(* Logix 5000 project; controller R21 vendor 1 type 14 code 96 rev 21.11; software revision 21.00; part 2 of 5 *)

ADD_ON_INSTRUCTION PSDNP3EventG20V05   (* revision 1.0, vendor ProSoft Technology Inc *)
VAR_IN_OUT
   EventBuffer : PSDNP3MasterEvent[1]; {required}
END_VAR
VAR_INPUT
   BufferSize : DINT; {required}
   CurrentBufferIndex : DINT; {required}
   Reset : BOOL; {required}
   OutstationNodeAddress : INT; {required}
   OutstationIPAddress0 : INT; {required}
   OutstationIPAddress1 : INT; {required}
   OutstationIPAddress2 : INT; {required}
   OutstationIPAddress3 : INT; {required}
END_VAR
VAR_IN_OUT
   DNP3StaticObject : DINT[1]; {required}
END_VAR
VAR_INPUT
   MaxtElementCount : DINT; {required}
END_VAR
VAR_OUTPUT
   EventsProcessed : DINT; {access Read Only, visible}
   LastElementIndex : DINT; {access Read Only, visible}
   LastValue : DINT; {access Read Only, visible}
   LastStatus : SINT; {access Read Only, visible}
   CurrentUnloadIndex : DINT; {access Read Only, visible}
END_VAR
VAR
   UnloadIndex : DINT; {access None}
   EnableInTemp : BOOL; {access None}
   InitialScan : BOOL; {access None}
   EntryValidForProcessing : BOOL; {access None}
   ElementIndex : DINT; {access None}
   NextIndex : DINT; {access None}
   ResetPulse : BOOL; {access None}
   ResetONS : BOOL; {access None}
END_VAR

ROUTINE Logic   (* ladder *)
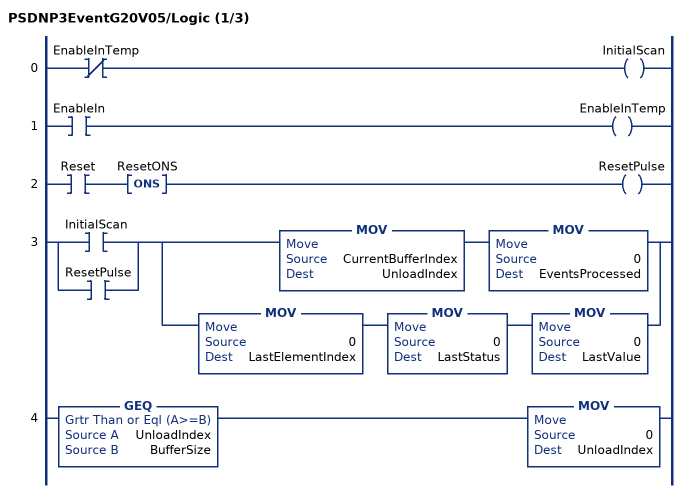
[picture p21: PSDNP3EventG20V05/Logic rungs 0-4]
   0: XIO(EnableInTemp)OTE(InitialScan);
   1: XIC(EnableIn)OTE(EnableInTemp);
   2: XIC(Reset)ONS(ResetONS)OTE(ResetPulse);
   3: [XIC(InitialScan) ,XIC(ResetPulse) ][MOV(CurrentBufferIndex,UnloadIndex) MOV(0,EventsProcessed) ,MOV(0,LastElementIndex) MOV(0,LastStatus) MOV(0,LastValue) ];
   4: GEQ(UnloadIndex,BufferSize)MOV(0,UnloadIndex);
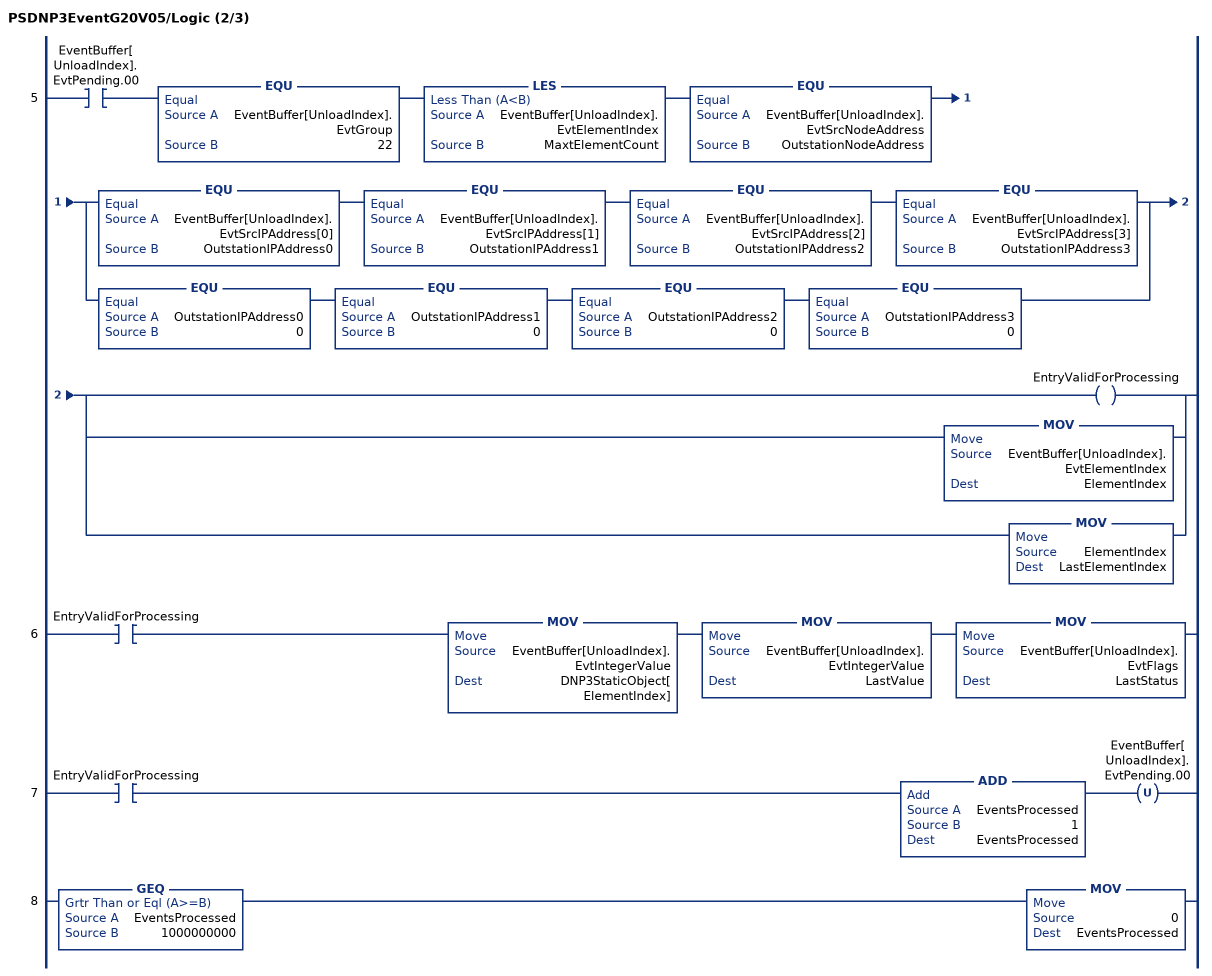
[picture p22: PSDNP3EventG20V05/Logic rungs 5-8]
   5: XIC(EventBuffer[UnloadIndex].EvtPending.00)EQU(EventBuffer[UnloadIndex].EvtGroup,22)LES(EventBuffer[UnloadIndex].EvtElementIndex,MaxtElementCount)EQU(EventBuffer[UnloadIndex].EvtSrcNodeAddress,OutstationNodeAddress)[EQU(EventBuffer[UnloadIndex].EvtSrcIPAddress[0],OutstationIPAddress0) EQU(EventBuffer[UnloadIndex].EvtSrcIPAddress[1],OutstationIPAddress1) EQU(EventBuffer[UnloadIndex].EvtSrcIPAddress[2],OutstationIPAddress2) EQU(EventBuffer[UnloadIndex].EvtSrcIPAddress[3],OutstationIPAddress3) ,EQU(OutstationIPAddress0,0) EQU(OutstationIPAddress1,0) EQU(OutstationIPAddress2,0) EQU(OutstationIPAddress3,0) ][OTE(EntryValidForProcessing) ,MOV(EventBuffer[UnloadIndex].EvtElementIndex,ElementIndex) ,MOV(ElementIndex,LastElementIndex) ];
   6: XIC(EntryValidForProcessing)MOV(EventBuffer[UnloadIndex].EvtIntegerValue,DNP3StaticObject[ElementIndex])MOV(EventBuffer[UnloadIndex].EvtIntegerValue,LastValue)MOV(EventBuffer[UnloadIndex].EvtFlags,LastStatus);
   7: XIC(EntryValidForProcessing)ADD(EventsProcessed,1,EventsProcessed)OTU(EventBuffer[UnloadIndex].EvtPending.00);
   8: GEQ(EventsProcessed,1000000000)MOV(0,EventsProcessed);
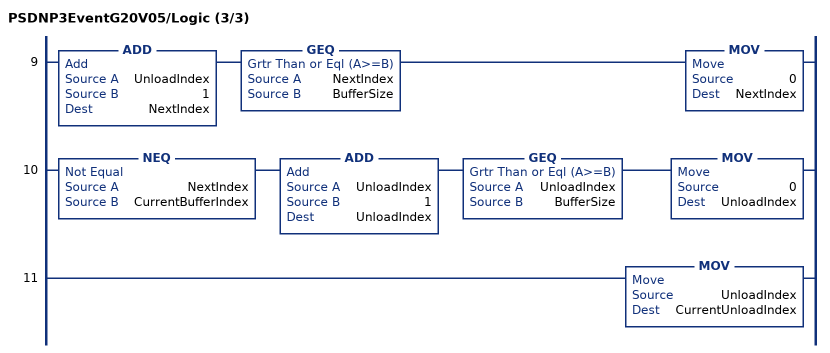
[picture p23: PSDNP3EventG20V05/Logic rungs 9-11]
   9: ADD(UnloadIndex,1,NextIndex)GEQ(NextIndex,BufferSize)MOV(0,NextIndex);
   10: NEQ(NextIndex,CurrentBufferIndex)ADD(UnloadIndex,1,UnloadIndex)GEQ(UnloadIndex,BufferSize)MOV(0,UnloadIndex);
   11: MOV(UnloadIndex,CurrentUnloadIndex);
END_ROUTINE
END_ADD_ON_INSTRUCTION

ADD_ON_INSTRUCTION PSDNP3EventG20V06   (* revision 1.0, vendor ProSoft Technology Inc *)
VAR_IN_OUT
   EventBuffer : PSDNP3MasterEvent[1]; {required}
END_VAR
VAR_INPUT
   BufferSize : DINT; {required}
   CurrentBufferIndex : DINT; {required}
   Reset : BOOL; {required}
   OutstationNodeAddress : INT; {required}
   OutstationIPAddress0 : INT; {required}
   OutstationIPAddress1 : INT; {required}
   OutstationIPAddress2 : INT; {required}
   OutstationIPAddress3 : INT; {required}
END_VAR
VAR_IN_OUT
   DNP3StaticObject : INT[1]; {required}
END_VAR
VAR_INPUT
   MaxtElementCount : DINT; {required}
END_VAR
VAR_OUTPUT
   EventsProcessed : DINT; {access Read Only, visible}
   LastElementIndex : DINT; {access Read Only, visible}
   LastValue : DINT; {access Read Only, visible}
   LastStatus : SINT; {access Read Only, visible}
   CurrentUnloadIndex : DINT; {access Read Only, visible}
END_VAR
VAR
   UnloadIndex : DINT; {access None}
   EnableInTemp : BOOL; {access None}
   InitialScan : BOOL; {access None}
   EntryValidForProcessing : BOOL; {access None}
   ElementIndex : DINT; {access None}
   NextIndex : DINT; {access None}
   ResetPulse : BOOL; {access None}
   ResetONS : BOOL; {access None}
END_VAR

ROUTINE Logic   (* ladder *)
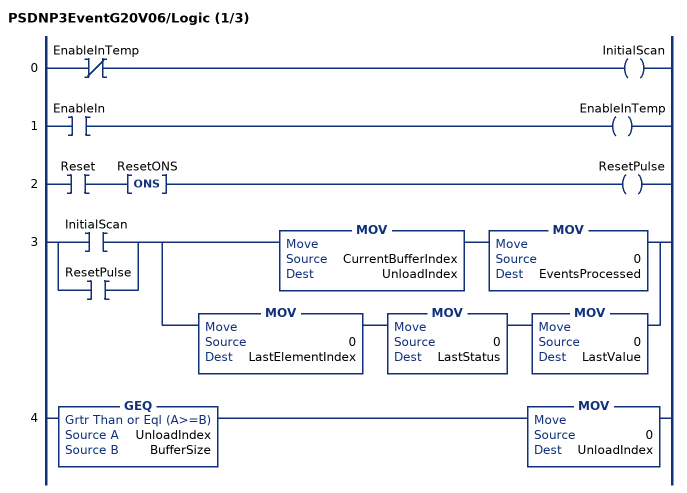
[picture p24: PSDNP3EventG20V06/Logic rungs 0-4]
   0: XIO(EnableInTemp)OTE(InitialScan);
   1: XIC(EnableIn)OTE(EnableInTemp);
   2: XIC(Reset)ONS(ResetONS)OTE(ResetPulse);
   3: [XIC(InitialScan) ,XIC(ResetPulse) ][MOV(CurrentBufferIndex,UnloadIndex) MOV(0,EventsProcessed) ,MOV(0,LastElementIndex) MOV(0,LastStatus) MOV(0,LastValue) ];
   4: GEQ(UnloadIndex,BufferSize)MOV(0,UnloadIndex);
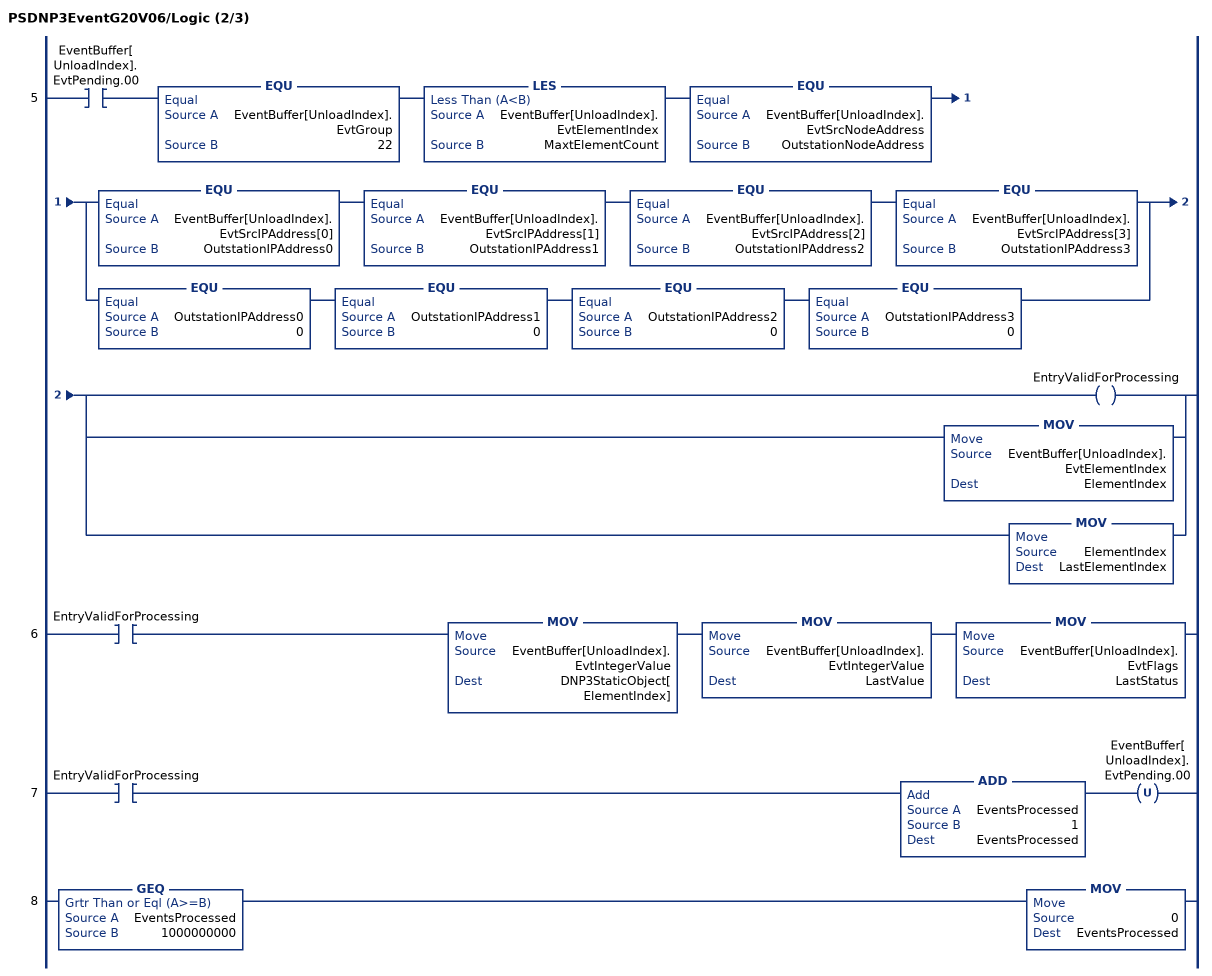
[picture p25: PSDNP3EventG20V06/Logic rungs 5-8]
   5: XIC(EventBuffer[UnloadIndex].EvtPending.00)EQU(EventBuffer[UnloadIndex].EvtGroup,22)LES(EventBuffer[UnloadIndex].EvtElementIndex,MaxtElementCount)EQU(EventBuffer[UnloadIndex].EvtSrcNodeAddress,OutstationNodeAddress)[EQU(EventBuffer[UnloadIndex].EvtSrcIPAddress[0],OutstationIPAddress0) EQU(EventBuffer[UnloadIndex].EvtSrcIPAddress[1],OutstationIPAddress1) EQU(EventBuffer[UnloadIndex].EvtSrcIPAddress[2],OutstationIPAddress2) EQU(EventBuffer[UnloadIndex].EvtSrcIPAddress[3],OutstationIPAddress3) ,EQU(OutstationIPAddress0,0) EQU(OutstationIPAddress1,0) EQU(OutstationIPAddress2,0) EQU(OutstationIPAddress3,0) ][OTE(EntryValidForProcessing) ,MOV(EventBuffer[UnloadIndex].EvtElementIndex,ElementIndex) ,MOV(ElementIndex,LastElementIndex) ];
   6: XIC(EntryValidForProcessing)MOV(EventBuffer[UnloadIndex].EvtIntegerValue,DNP3StaticObject[ElementIndex])MOV(EventBuffer[UnloadIndex].EvtIntegerValue,LastValue)MOV(EventBuffer[UnloadIndex].EvtFlags,LastStatus);
   7: XIC(EntryValidForProcessing)ADD(EventsProcessed,1,EventsProcessed)OTU(EventBuffer[UnloadIndex].EvtPending.00);
   8: GEQ(EventsProcessed,1000000000)MOV(0,EventsProcessed);
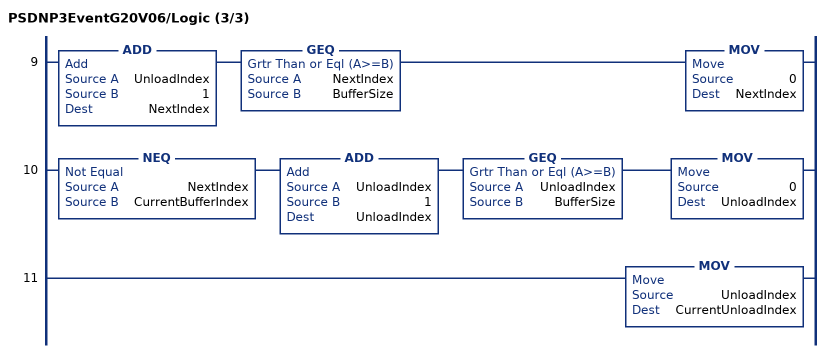
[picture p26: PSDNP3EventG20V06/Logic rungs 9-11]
   9: ADD(UnloadIndex,1,NextIndex)GEQ(NextIndex,BufferSize)MOV(0,NextIndex);
   10: NEQ(NextIndex,CurrentBufferIndex)ADD(UnloadIndex,1,UnloadIndex)GEQ(UnloadIndex,BufferSize)MOV(0,UnloadIndex);
   11: MOV(UnloadIndex,CurrentUnloadIndex);
END_ROUTINE
END_ADD_ON_INSTRUCTION

ADD_ON_INSTRUCTION PSDNP3EventG21V01   (* revision 1.0, vendor ProSoft Technology Inc *)
VAR_IN_OUT
   EventBuffer : PSDNP3MasterEvent[1]; {required}
END_VAR
VAR_INPUT
   BufferSize : DINT; {required}
   CurrentBufferIndex : DINT; {required}
   Reset : BOOL; {required}
   OutstationNodeAddress : INT; {required}
   OutstationIPAddress0 : INT; {required}
   OutstationIPAddress1 : INT; {required}
   OutstationIPAddress2 : INT; {required}
   OutstationIPAddress3 : INT; {required}
END_VAR
VAR_IN_OUT
   DNP3StaticObject : PSDNP3FrozenCounter32WithFlag[1]; {required}
END_VAR
VAR_INPUT
   MaxtElementCount : DINT; {required}
END_VAR
VAR_OUTPUT
   EventsProcessed : DINT; {access Read Only, visible}
   LastElementIndex : DINT; {access Read Only, visible}
   LastValue : DINT; {access Read Only, visible}
   LastStatus : SINT; {access Read Only, visible}
   CurrentUnloadIndex : DINT; {access Read Only, visible}
END_VAR
VAR
   UnloadIndex : DINT; {access None}
   EnableInTemp : BOOL; {access None}
   InitialScan : BOOL; {access None}
   EntryValidForProcessing : BOOL; {access None}
   ElementIndex : DINT; {access None}
   NextIndex : DINT; {access None}
   ResetPulse : BOOL; {access None}
   ResetONS : BOOL; {access None}
END_VAR

ROUTINE Logic   (* ladder *)
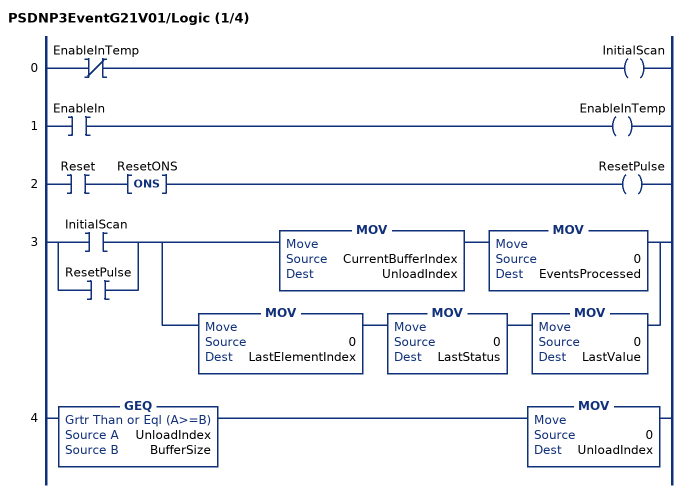
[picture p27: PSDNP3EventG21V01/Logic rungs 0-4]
   0: XIO(EnableInTemp)OTE(InitialScan);
   1: XIC(EnableIn)OTE(EnableInTemp);
   2: XIC(Reset)ONS(ResetONS)OTE(ResetPulse);
   3: [XIC(InitialScan) ,XIC(ResetPulse) ][MOV(CurrentBufferIndex,UnloadIndex) MOV(0,EventsProcessed) ,MOV(0,LastElementIndex) MOV(0,LastStatus) MOV(0,LastValue) ];
   4: GEQ(UnloadIndex,BufferSize)MOV(0,UnloadIndex);
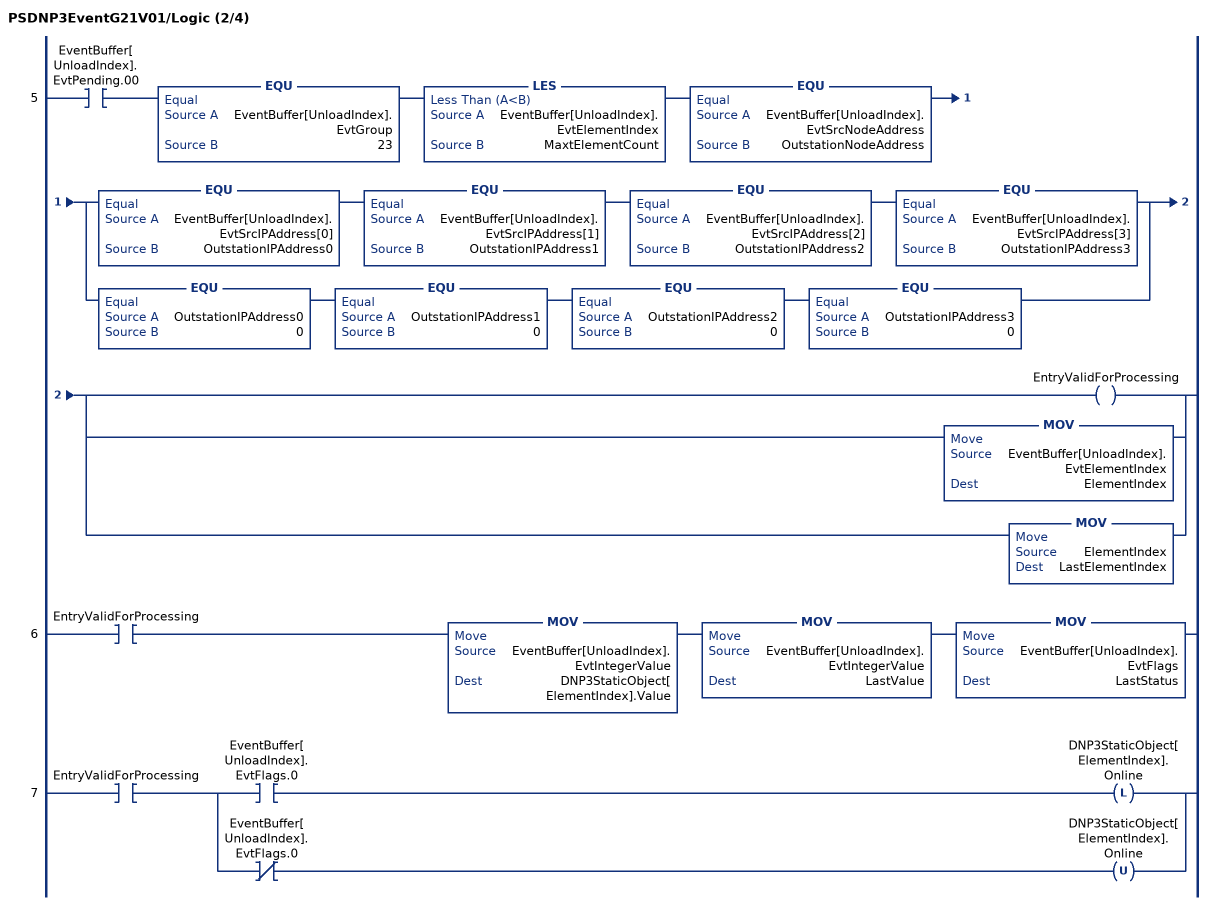
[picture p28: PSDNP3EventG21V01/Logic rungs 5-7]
   5: XIC(EventBuffer[UnloadIndex].EvtPending.00)EQU(EventBuffer[UnloadIndex].EvtGroup,23)LES(EventBuffer[UnloadIndex].EvtElementIndex,MaxtElementCount)EQU(EventBuffer[UnloadIndex].EvtSrcNodeAddress,OutstationNodeAddress)[EQU(EventBuffer[UnloadIndex].EvtSrcIPAddress[0],OutstationIPAddress0) EQU(EventBuffer[UnloadIndex].EvtSrcIPAddress[1],OutstationIPAddress1) EQU(EventBuffer[UnloadIndex].EvtSrcIPAddress[2],OutstationIPAddress2) EQU(EventBuffer[UnloadIndex].EvtSrcIPAddress[3],OutstationIPAddress3) ,EQU(OutstationIPAddress0,0) EQU(OutstationIPAddress1,0) EQU(OutstationIPAddress2,0) EQU(OutstationIPAddress3,0) ][OTE(EntryValidForProcessing) ,MOV(EventBuffer[UnloadIndex].EvtElementIndex,ElementIndex) ,MOV(ElementIndex,LastElementIndex) ];
   6: XIC(EntryValidForProcessing)MOV(EventBuffer[UnloadIndex].EvtIntegerValue,DNP3StaticObject[ElementIndex].Value)MOV(EventBuffer[UnloadIndex].EvtIntegerValue,LastValue)MOV(EventBuffer[UnloadIndex].EvtFlags,LastStatus);
   7: XIC(EntryValidForProcessing)[XIC(EventBuffer[UnloadIndex].EvtFlags.0) OTL(DNP3StaticObject[ElementIndex].Online) ,XIO(EventBuffer[UnloadIndex].EvtFlags.0) OTU(DNP3StaticObject[ElementIndex].Online) ];
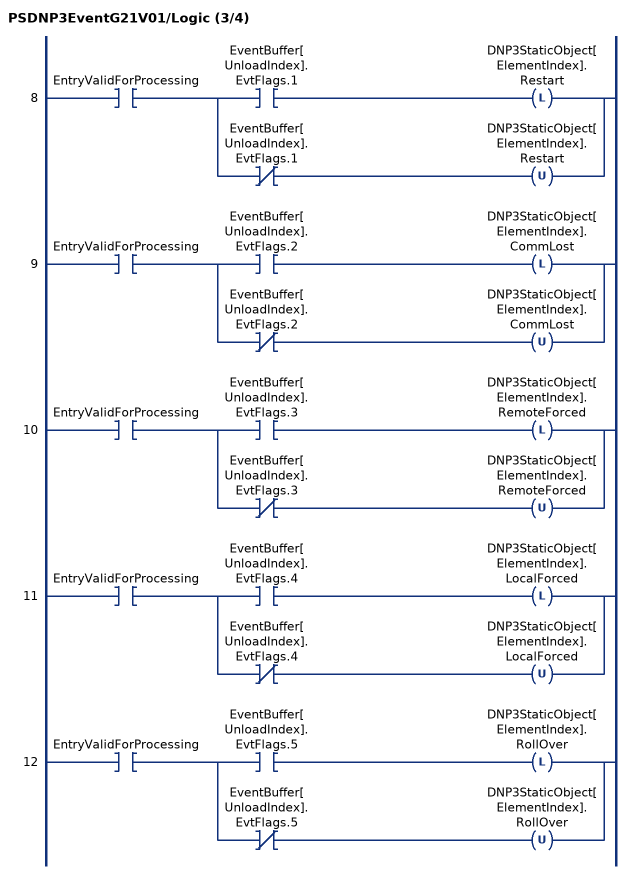
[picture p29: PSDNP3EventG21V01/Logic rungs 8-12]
   8: XIC(EntryValidForProcessing)[XIC(EventBuffer[UnloadIndex].EvtFlags.1) OTL(DNP3StaticObject[ElementIndex].Restart) ,XIO(EventBuffer[UnloadIndex].EvtFlags.1) OTU(DNP3StaticObject[ElementIndex].Restart) ];
   9: XIC(EntryValidForProcessing)[XIC(EventBuffer[UnloadIndex].EvtFlags.2) OTL(DNP3StaticObject[ElementIndex].CommLost) ,XIO(EventBuffer[UnloadIndex].EvtFlags.2) OTU(DNP3StaticObject[ElementIndex].CommLost) ];
   10: XIC(EntryValidForProcessing)[XIC(EventBuffer[UnloadIndex].EvtFlags.3) OTL(DNP3StaticObject[ElementIndex].RemoteForced) ,XIO(EventBuffer[UnloadIndex].EvtFlags.3) OTU(DNP3StaticObject[ElementIndex].RemoteForced) ];
   11: XIC(EntryValidForProcessing)[XIC(EventBuffer[UnloadIndex].EvtFlags.4) OTL(DNP3StaticObject[ElementIndex].LocalForced) ,XIO(EventBuffer[UnloadIndex].EvtFlags.4) OTU(DNP3StaticObject[ElementIndex].LocalForced) ];
   12: XIC(EntryValidForProcessing)[XIC(EventBuffer[UnloadIndex].EvtFlags.5) OTL(DNP3StaticObject[ElementIndex].RollOver) ,XIO(EventBuffer[UnloadIndex].EvtFlags.5) OTU(DNP3StaticObject[ElementIndex].RollOver) ];
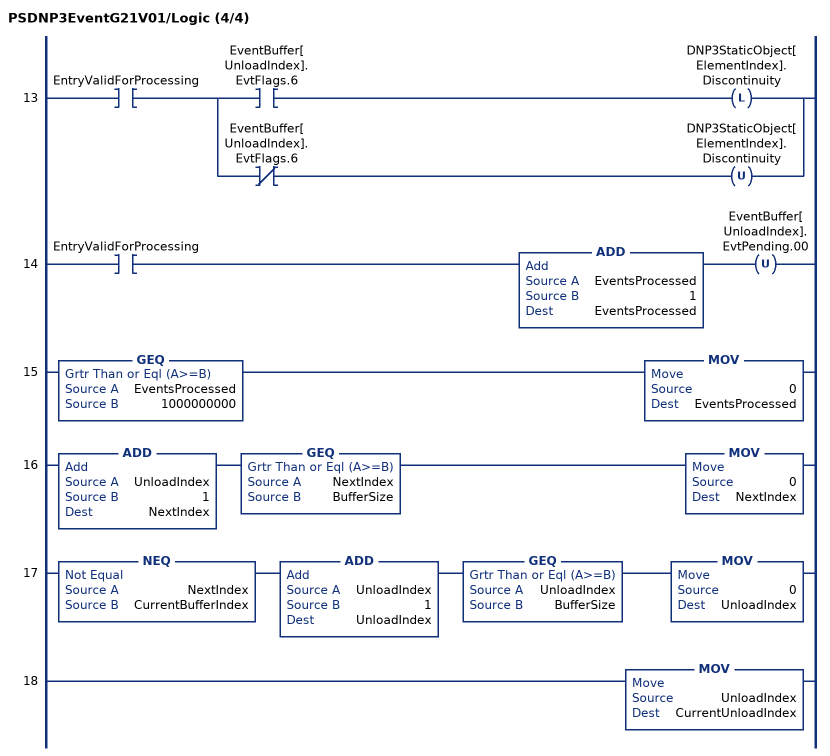
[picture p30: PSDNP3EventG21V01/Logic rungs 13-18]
   13: XIC(EntryValidForProcessing)[XIC(EventBuffer[UnloadIndex].EvtFlags.6) OTL(DNP3StaticObject[ElementIndex].Discontinuity) ,XIO(EventBuffer[UnloadIndex].EvtFlags.6) OTU(DNP3StaticObject[ElementIndex].Discontinuity) ];
   14: XIC(EntryValidForProcessing)ADD(EventsProcessed,1,EventsProcessed)OTU(EventBuffer[UnloadIndex].EvtPending.00);
   15: GEQ(EventsProcessed,1000000000)MOV(0,EventsProcessed);
   16: ADD(UnloadIndex,1,NextIndex)GEQ(NextIndex,BufferSize)MOV(0,NextIndex);
   17: NEQ(NextIndex,CurrentBufferIndex)ADD(UnloadIndex,1,UnloadIndex)GEQ(UnloadIndex,BufferSize)MOV(0,UnloadIndex);
   18: MOV(UnloadIndex,CurrentUnloadIndex);
END_ROUTINE
END_ADD_ON_INSTRUCTION

ADD_ON_INSTRUCTION PSDNP3EventG21V02   (* revision 1.0, vendor ProSoft Technology Inc *)
VAR_IN_OUT
   EventBuffer : PSDNP3MasterEvent[1]; {required}
END_VAR
VAR_INPUT
   BufferSize : DINT; {required}
   CurrentBufferIndex : DINT; {required}
   Reset : BOOL; {required}
   OutstationNodeAddress : INT; {required}
   OutstationIPAddress0 : INT; {required}
   OutstationIPAddress1 : INT; {required}
   OutstationIPAddress2 : INT; {required}
   OutstationIPAddress3 : INT; {required}
END_VAR
VAR_IN_OUT
   DNP3StaticObject : PSDNP3FrozenCounter16WithFlag[1]; {required}
END_VAR
VAR_INPUT
   MaxtElementCount : DINT; {required}
END_VAR
VAR_OUTPUT
   EventsProcessed : DINT; {access Read Only, visible}
   LastElementIndex : DINT; {access Read Only, visible}
   LastValue : DINT; {access Read Only, visible}
   LastStatus : SINT; {access Read Only, visible}
   CurrentUnloadIndex : DINT; {access Read Only, visible}
END_VAR
VAR
   UnloadIndex : DINT; {access None}
   EnableInTemp : BOOL; {access None}
   InitialScan : BOOL; {access None}
   EntryValidForProcessing : BOOL; {access None}
   ElementIndex : DINT; {access None}
   NextIndex : DINT; {access None}
   ResetPulse : BOOL; {access None}
   ResetONS : BOOL; {access None}
END_VAR

ROUTINE Logic   (* ladder *)
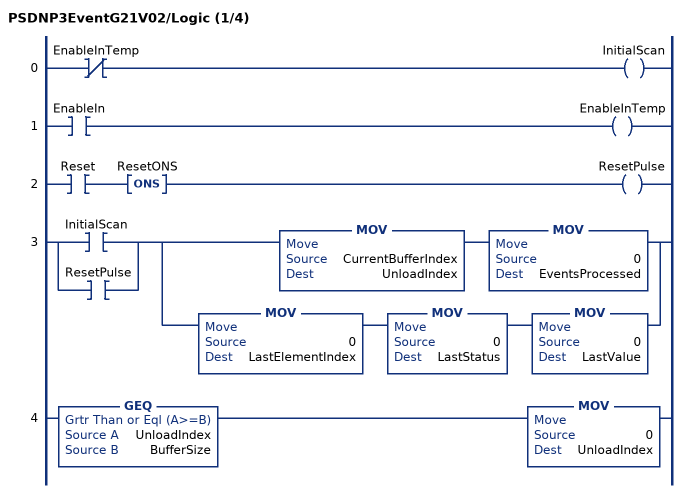
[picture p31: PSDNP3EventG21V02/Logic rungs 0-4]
   0: XIO(EnableInTemp)OTE(InitialScan);
   1: XIC(EnableIn)OTE(EnableInTemp);
   2: XIC(Reset)ONS(ResetONS)OTE(ResetPulse);
   3: [XIC(InitialScan) ,XIC(ResetPulse) ][MOV(CurrentBufferIndex,UnloadIndex) MOV(0,EventsProcessed) ,MOV(0,LastElementIndex) MOV(0,LastStatus) MOV(0,LastValue) ];
   4: GEQ(UnloadIndex,BufferSize)MOV(0,UnloadIndex);
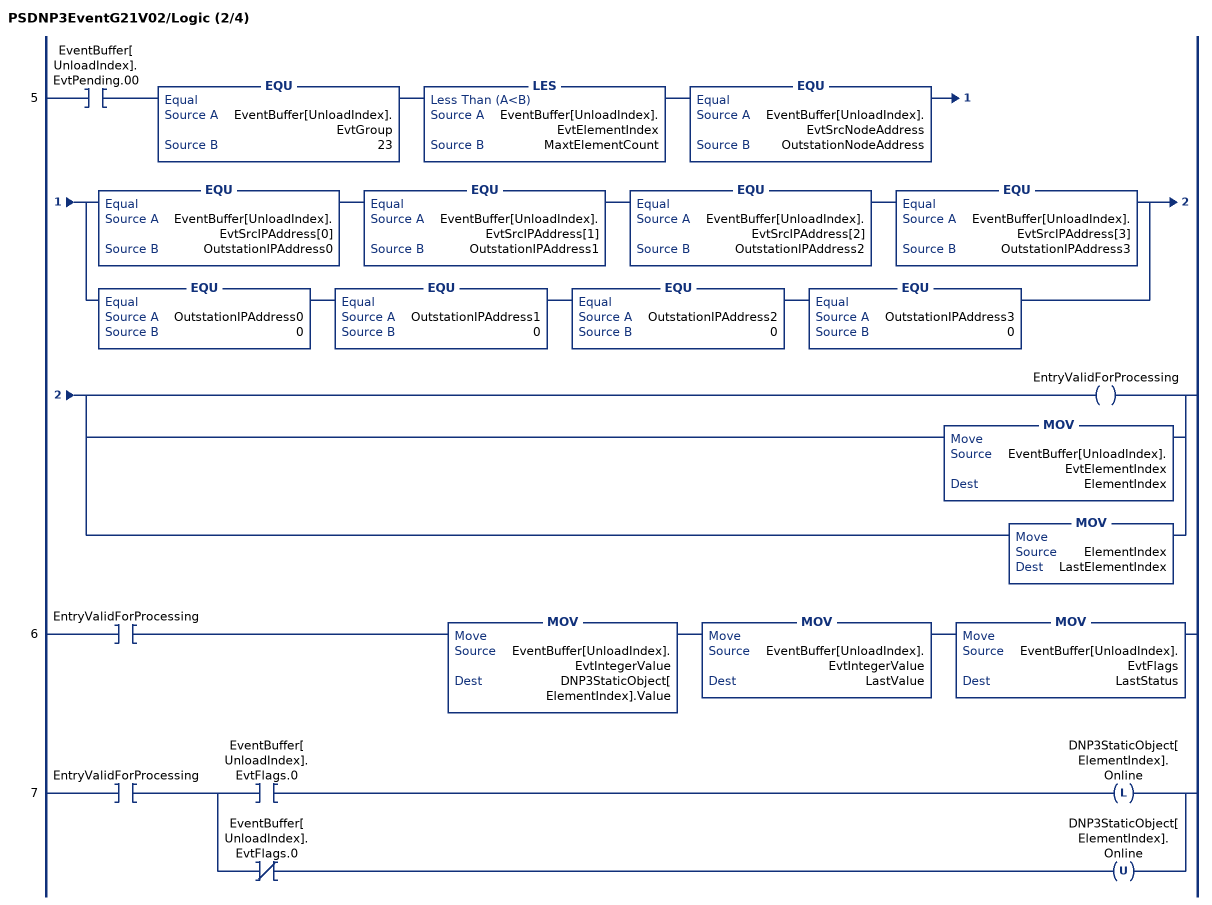
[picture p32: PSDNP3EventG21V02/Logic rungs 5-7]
   5: XIC(EventBuffer[UnloadIndex].EvtPending.00)EQU(EventBuffer[UnloadIndex].EvtGroup,23)LES(EventBuffer[UnloadIndex].EvtElementIndex,MaxtElementCount)EQU(EventBuffer[UnloadIndex].EvtSrcNodeAddress,OutstationNodeAddress)[EQU(EventBuffer[UnloadIndex].EvtSrcIPAddress[0],OutstationIPAddress0) EQU(EventBuffer[UnloadIndex].EvtSrcIPAddress[1],OutstationIPAddress1) EQU(EventBuffer[UnloadIndex].EvtSrcIPAddress[2],OutstationIPAddress2) EQU(EventBuffer[UnloadIndex].EvtSrcIPAddress[3],OutstationIPAddress3) ,EQU(OutstationIPAddress0,0) EQU(OutstationIPAddress1,0) EQU(OutstationIPAddress2,0) EQU(OutstationIPAddress3,0) ][OTE(EntryValidForProcessing) ,MOV(EventBuffer[UnloadIndex].EvtElementIndex,ElementIndex) ,MOV(ElementIndex,LastElementIndex) ];
   6: XIC(EntryValidForProcessing)MOV(EventBuffer[UnloadIndex].EvtIntegerValue,DNP3StaticObject[ElementIndex].Value)MOV(EventBuffer[UnloadIndex].EvtIntegerValue,LastValue)MOV(EventBuffer[UnloadIndex].EvtFlags,LastStatus);
   7: XIC(EntryValidForProcessing)[XIC(EventBuffer[UnloadIndex].EvtFlags.0) OTL(DNP3StaticObject[ElementIndex].Online) ,XIO(EventBuffer[UnloadIndex].EvtFlags.0) OTU(DNP3StaticObject[ElementIndex].Online) ];
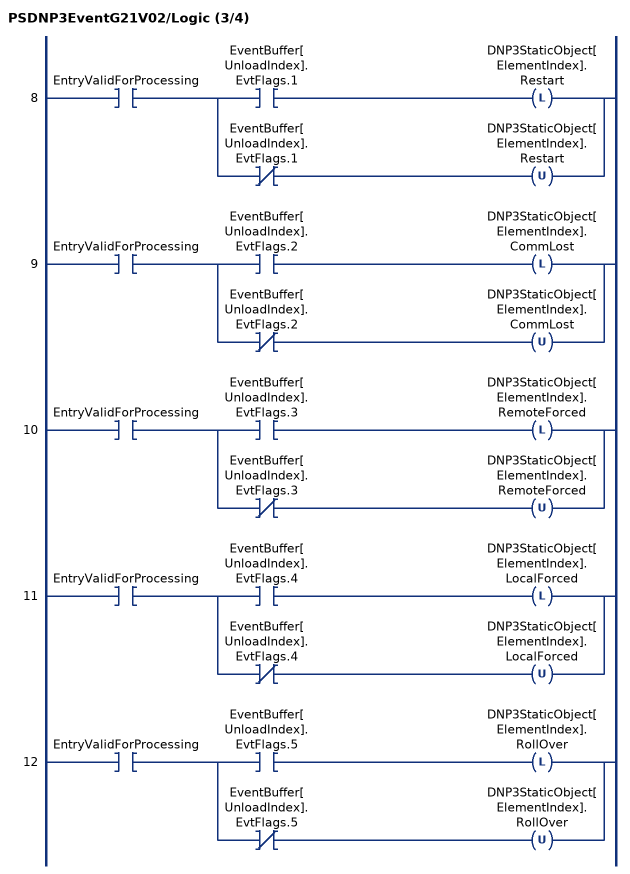
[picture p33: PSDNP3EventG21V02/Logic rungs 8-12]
   8: XIC(EntryValidForProcessing)[XIC(EventBuffer[UnloadIndex].EvtFlags.1) OTL(DNP3StaticObject[ElementIndex].Restart) ,XIO(EventBuffer[UnloadIndex].EvtFlags.1) OTU(DNP3StaticObject[ElementIndex].Restart) ];
   9: XIC(EntryValidForProcessing)[XIC(EventBuffer[UnloadIndex].EvtFlags.2) OTL(DNP3StaticObject[ElementIndex].CommLost) ,XIO(EventBuffer[UnloadIndex].EvtFlags.2) OTU(DNP3StaticObject[ElementIndex].CommLost) ];
   10: XIC(EntryValidForProcessing)[XIC(EventBuffer[UnloadIndex].EvtFlags.3) OTL(DNP3StaticObject[ElementIndex].RemoteForced) ,XIO(EventBuffer[UnloadIndex].EvtFlags.3) OTU(DNP3StaticObject[ElementIndex].RemoteForced) ];
   11: XIC(EntryValidForProcessing)[XIC(EventBuffer[UnloadIndex].EvtFlags.4) OTL(DNP3StaticObject[ElementIndex].LocalForced) ,XIO(EventBuffer[UnloadIndex].EvtFlags.4) OTU(DNP3StaticObject[ElementIndex].LocalForced) ];
   12: XIC(EntryValidForProcessing)[XIC(EventBuffer[UnloadIndex].EvtFlags.5) OTL(DNP3StaticObject[ElementIndex].RollOver) ,XIO(EventBuffer[UnloadIndex].EvtFlags.5) OTU(DNP3StaticObject[ElementIndex].RollOver) ];
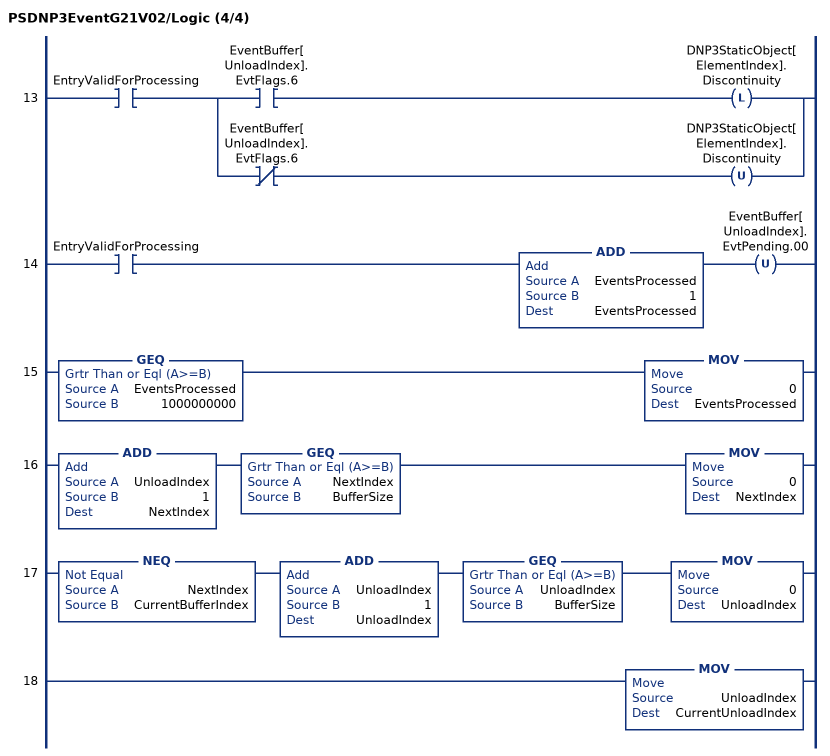
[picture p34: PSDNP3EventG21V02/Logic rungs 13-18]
   13: XIC(EntryValidForProcessing)[XIC(EventBuffer[UnloadIndex].EvtFlags.6) OTL(DNP3StaticObject[ElementIndex].Discontinuity) ,XIO(EventBuffer[UnloadIndex].EvtFlags.6) OTU(DNP3StaticObject[ElementIndex].Discontinuity) ];
   14: XIC(EntryValidForProcessing)ADD(EventsProcessed,1,EventsProcessed)OTU(EventBuffer[UnloadIndex].EvtPending.00);
   15: GEQ(EventsProcessed,1000000000)MOV(0,EventsProcessed);
   16: ADD(UnloadIndex,1,NextIndex)GEQ(NextIndex,BufferSize)MOV(0,NextIndex);
   17: NEQ(NextIndex,CurrentBufferIndex)ADD(UnloadIndex,1,UnloadIndex)GEQ(UnloadIndex,BufferSize)MOV(0,UnloadIndex);
   18: MOV(UnloadIndex,CurrentUnloadIndex);
END_ROUTINE
END_ADD_ON_INSTRUCTION

ADD_ON_INSTRUCTION PSDNP3EventG21V05   (* revision 1.0, vendor ProSoft Technology Inc *)
VAR_IN_OUT
   EventBuffer : PSDNP3MasterEvent[1]; {required}
END_VAR
VAR_INPUT
   BufferSize : DINT; {required}
   CurrentBufferIndex : DINT; {required}
   Reset : BOOL; {required}
   OutstationNodeAddress : INT; {required}
   OutstationIPAddress0 : INT; {required}
   OutstationIPAddress1 : INT; {required}
   OutstationIPAddress2 : INT; {required}
   OutstationIPAddress3 : INT; {required}
END_VAR
VAR_IN_OUT
   DNP3StaticObject : PSDNP3FrozenCounter32WithFlagTime[1]; {required}
END_VAR
VAR_INPUT
   MaxtElementCount : DINT; {required}
END_VAR
VAR_OUTPUT
   EventsProcessed : DINT; {access Read Only, visible}
   LastElementIndex : DINT; {access Read Only, visible}
   LastValue : DINT; {access Read Only, visible}
   LastStatus : SINT; {access Read Only, visible}
   CurrentUnloadIndex : DINT; {access Read Only, visible}
END_VAR
VAR
   UnloadIndex : DINT; {access None}
   EnableInTemp : BOOL; {access None}
   InitialScan : BOOL; {access None}
   EntryValidForProcessing : BOOL; {access None}
   ElementIndex : DINT; {access None}
   NextIndex : DINT; {access None}
   ResetPulse : BOOL; {access None}
   ResetONS : BOOL; {access None}
END_VAR

ROUTINE Logic   (* ladder *)
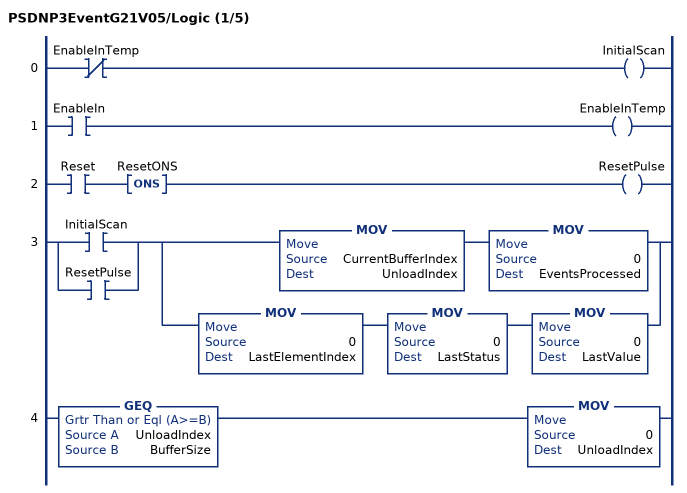
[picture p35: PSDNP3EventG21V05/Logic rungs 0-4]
   0: XIO(EnableInTemp)OTE(InitialScan);
   1: XIC(EnableIn)OTE(EnableInTemp);
   2: XIC(Reset)ONS(ResetONS)OTE(ResetPulse);
   3: [XIC(InitialScan) ,XIC(ResetPulse) ][MOV(CurrentBufferIndex,UnloadIndex) MOV(0,EventsProcessed) ,MOV(0,LastElementIndex) MOV(0,LastStatus) MOV(0,LastValue) ];
   4: GEQ(UnloadIndex,BufferSize)MOV(0,UnloadIndex);
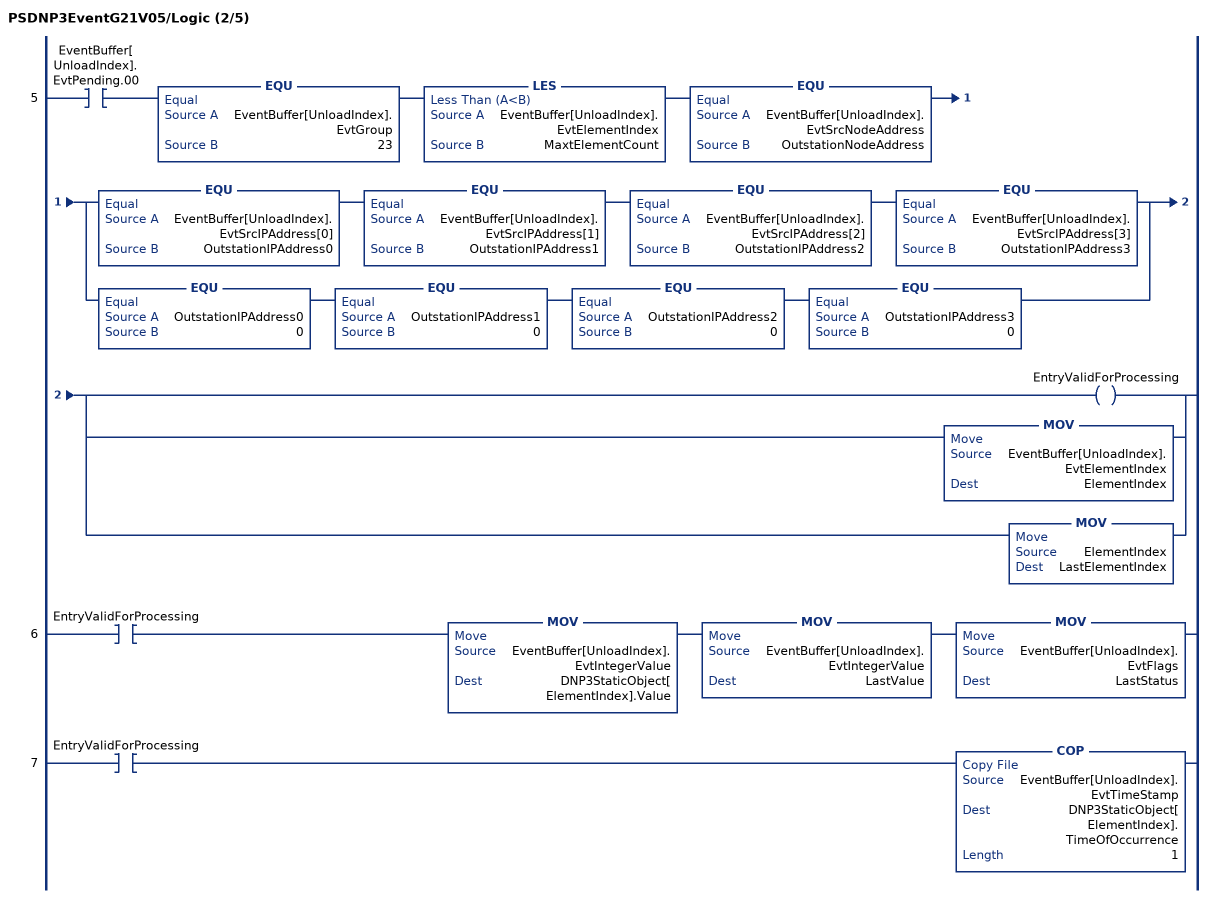
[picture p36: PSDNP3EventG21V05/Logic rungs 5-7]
   5: XIC(EventBuffer[UnloadIndex].EvtPending.00)EQU(EventBuffer[UnloadIndex].EvtGroup,23)LES(EventBuffer[UnloadIndex].EvtElementIndex,MaxtElementCount)EQU(EventBuffer[UnloadIndex].EvtSrcNodeAddress,OutstationNodeAddress)[EQU(EventBuffer[UnloadIndex].EvtSrcIPAddress[0],OutstationIPAddress0) EQU(EventBuffer[UnloadIndex].EvtSrcIPAddress[1],OutstationIPAddress1) EQU(EventBuffer[UnloadIndex].EvtSrcIPAddress[2],OutstationIPAddress2) EQU(EventBuffer[UnloadIndex].EvtSrcIPAddress[3],OutstationIPAddress3) ,EQU(OutstationIPAddress0,0) EQU(OutstationIPAddress1,0) EQU(OutstationIPAddress2,0) EQU(OutstationIPAddress3,0) ][OTE(EntryValidForProcessing) ,MOV(EventBuffer[UnloadIndex].EvtElementIndex,ElementIndex) ,MOV(ElementIndex,LastElementIndex) ];
   6: XIC(EntryValidForProcessing)MOV(EventBuffer[UnloadIndex].EvtIntegerValue,DNP3StaticObject[ElementIndex].Value)MOV(EventBuffer[UnloadIndex].EvtIntegerValue,LastValue)MOV(EventBuffer[UnloadIndex].EvtFlags,LastStatus);
   7: XIC(EntryValidForProcessing)COP(EventBuffer[UnloadIndex].EvtTimeStamp,DNP3StaticObject[ElementIndex].TimeOfOccurrence,1);
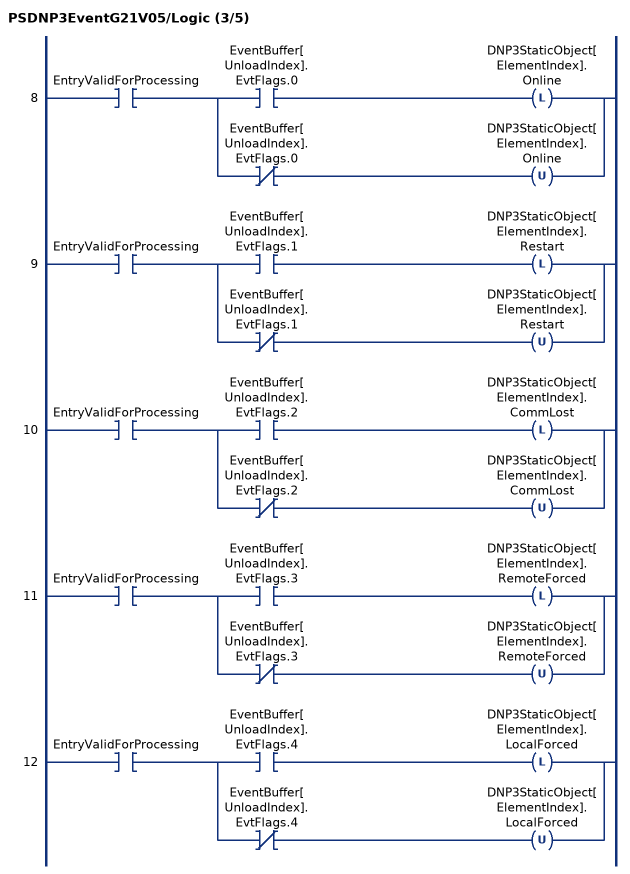
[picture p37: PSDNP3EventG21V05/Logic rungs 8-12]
   8: XIC(EntryValidForProcessing)[XIC(EventBuffer[UnloadIndex].EvtFlags.0) OTL(DNP3StaticObject[ElementIndex].Online) ,XIO(EventBuffer[UnloadIndex].EvtFlags.0) OTU(DNP3StaticObject[ElementIndex].Online) ];
   9: XIC(EntryValidForProcessing)[XIC(EventBuffer[UnloadIndex].EvtFlags.1) OTL(DNP3StaticObject[ElementIndex].Restart) ,XIO(EventBuffer[UnloadIndex].EvtFlags.1) OTU(DNP3StaticObject[ElementIndex].Restart) ];
   10: XIC(EntryValidForProcessing)[XIC(EventBuffer[UnloadIndex].EvtFlags.2) OTL(DNP3StaticObject[ElementIndex].CommLost) ,XIO(EventBuffer[UnloadIndex].EvtFlags.2) OTU(DNP3StaticObject[ElementIndex].CommLost) ];
   11: XIC(EntryValidForProcessing)[XIC(EventBuffer[UnloadIndex].EvtFlags.3) OTL(DNP3StaticObject[ElementIndex].RemoteForced) ,XIO(EventBuffer[UnloadIndex].EvtFlags.3) OTU(DNP3StaticObject[ElementIndex].RemoteForced) ];
   12: XIC(EntryValidForProcessing)[XIC(EventBuffer[UnloadIndex].EvtFlags.4) OTL(DNP3StaticObject[ElementIndex].LocalForced) ,XIO(EventBuffer[UnloadIndex].EvtFlags.4) OTU(DNP3StaticObject[ElementIndex].LocalForced) ];
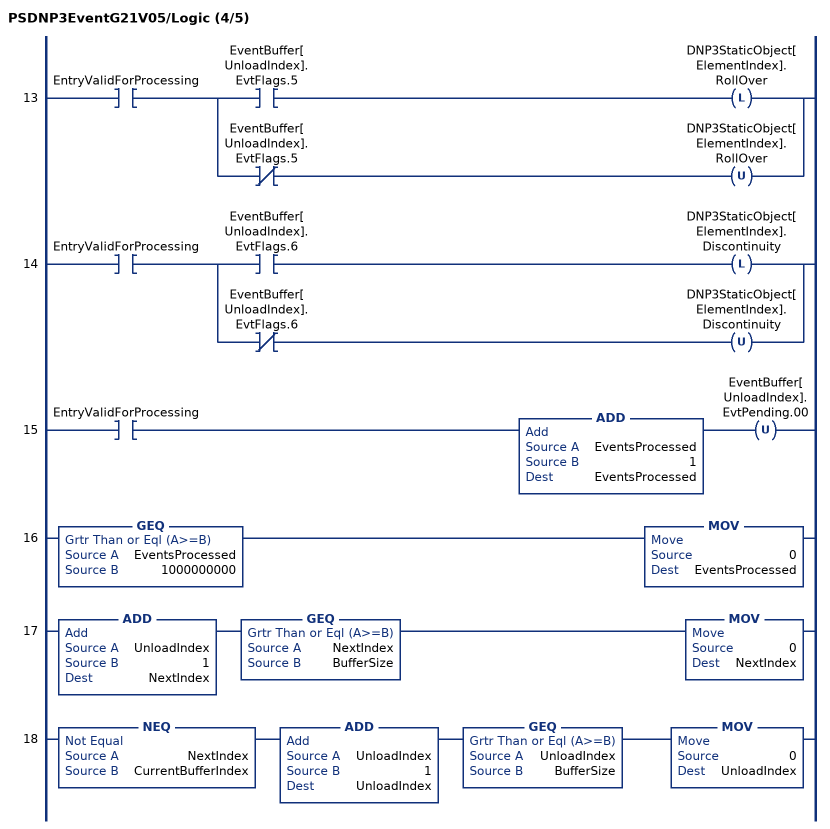
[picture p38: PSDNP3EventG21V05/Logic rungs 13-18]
   13: XIC(EntryValidForProcessing)[XIC(EventBuffer[UnloadIndex].EvtFlags.5) OTL(DNP3StaticObject[ElementIndex].RollOver) ,XIO(EventBuffer[UnloadIndex].EvtFlags.5) OTU(DNP3StaticObject[ElementIndex].RollOver) ];
   14: XIC(EntryValidForProcessing)[XIC(EventBuffer[UnloadIndex].EvtFlags.6) OTL(DNP3StaticObject[ElementIndex].Discontinuity) ,XIO(EventBuffer[UnloadIndex].EvtFlags.6) OTU(DNP3StaticObject[ElementIndex].Discontinuity) ];
   15: XIC(EntryValidForProcessing)ADD(EventsProcessed,1,EventsProcessed)OTU(EventBuffer[UnloadIndex].EvtPending.00);
   16: GEQ(EventsProcessed,1000000000)MOV(0,EventsProcessed);
   17: ADD(UnloadIndex,1,NextIndex)GEQ(NextIndex,BufferSize)MOV(0,NextIndex);
   18: NEQ(NextIndex,CurrentBufferIndex)ADD(UnloadIndex,1,UnloadIndex)GEQ(UnloadIndex,BufferSize)MOV(0,UnloadIndex);
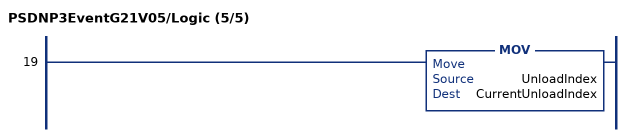
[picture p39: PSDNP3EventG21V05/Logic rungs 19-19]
   19: MOV(UnloadIndex,CurrentUnloadIndex);
END_ROUTINE
END_ADD_ON_INSTRUCTION
